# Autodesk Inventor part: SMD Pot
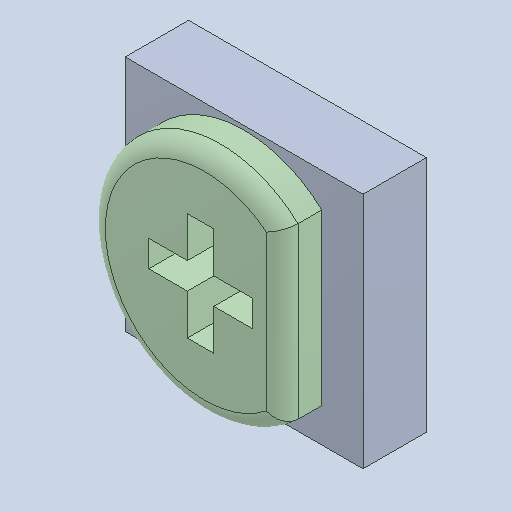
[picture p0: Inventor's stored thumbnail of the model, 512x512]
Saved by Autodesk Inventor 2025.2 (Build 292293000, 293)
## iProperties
Created: 2025-04
Part Number: SMD Pot
Material: Generic
Description: PART--DESC
Document SubType Name: Modeling
Designer: BennF
Density: 1 g/cm^3
Appearance: Default
Author: BennF
Revision Number: NONE
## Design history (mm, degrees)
feature "Solid1"
body "Solid2"
